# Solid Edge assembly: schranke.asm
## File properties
Author: Wir
Template: Normal.asm
Last saved by: Wir
Revision: 4
Application: Solid Edge
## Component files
Grundplatte.par
tze.par
Schrankenlager.par
Kurbel.par
Schranke.par
